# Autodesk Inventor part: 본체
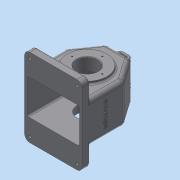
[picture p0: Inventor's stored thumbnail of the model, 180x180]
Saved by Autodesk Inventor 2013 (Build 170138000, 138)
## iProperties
Created: 2016-12
Part Number: 본체
Material: 일반
Document SubType Name: Modeling
Designer: dgall
Density: 1 g/cm^3
Author: dgall
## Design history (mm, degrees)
sketch "스케치1"
  geometry: L1 (-23.491, 85)-(-55, 40); L2 (-55, 40)-(-55, -40); L3 (-55, -40)-(55, -40); L4 (55, -40)-(55, 40); L5 (55, 40)-(23.491, 85); L6 (23.491, 85)-(-23.491, 85); L7 (-20.888, 80)-(-50, 38.424); L8 (-50, 38.424)-(-50, -40); L9 (50, -40)-(50, 38.424); L10 (50, 38.424)-(20.888, 80); L11 (20.888, 80)-(-20.888, 80); 4 further points
  constraints: 22 end point, 3 midpoint, 3 point on line, 2 vertical, 2 vertical alignment, 1 equal length, 1 horizontal, 1 horizontal alignment, 1 perpendicular, 3 other
  dimensions: "d0" = 80 distance of L3.end L4.end; "d2" = 35 deg angle of L2 L1; "d4" = 35 deg angle of L4 L5; "d6" = 125 distance between parallel lines of L3 L6; "d7" = 110 distance of L2.end L3.end; "d8" = 5 distance between parallel lines of L5 L10; "d9" = 5 distance between parallel lines of L1 L7
extrude "돌출1" new body sketch "스케치1" stored distance "d10" = 77; taper "d11" = 0 deg
extrude "돌출2" cut sketch "스케치1" stored distance "d12" = 67; taper "d13" = 0 deg
sketch "스케치2"
  geometry: L1 (85, -38.5)-(-40, -38.5) reference; L2 (-40, -38.5)-(-40, -33.5) reference; L3 (-40, -33.5)-(80, -33.5) reference; L4 (80, -33.5)-(80, 33.5) reference; L5 (80, 33.5)-(-40, 33.5) reference; L6 (-40, 33.5)-(-40, 38.5) reference; L7 (-40, 38.5)-(85, 38.5) reference; L8 (85, 38.5)-(85, -38.5) reference; L9 (25, 38.5)-(25, -38.5); L10 (-40, -33.5)-(-40, 33.5) reference; L11 (66, 33.5)-(52, 19.5); L12 (52, 19.5)-(25, 19.5); L13 (25, 38.5)-(25, 43.5); L14 (25, 43.5)-(62.5, 43.5); L15 (62.5, 43.5)-(62.5, 38.5); L16 (66, 33.5)-(66, 38.5); L17 (62.5, 38.5)-(66, 38.5); 1 further point
  constraints: 16 end point, 6 perpendicular, 6 point on line, 1 collinear
  dimensions: "d14" = 65 distance between parallel lines of L10 L9; "d16" = 24 distance between parallel lines of L12 L14; "d17" = 45 deg angle of L12 L11; "d18" = 5 distance from line of L14.end L7; "d19" = 27 distance from line of L9 L11.end; "d20" = 37.5 distance between parallel lines of L9 L15
revolve "회전1" sketch "스케치2" stored, may be unused: angle "d21" = 90 deg
node "작업 평면1"
sketch "스케치3" dims "d25" = 52
  geometry: C1 r 37.5 at (0, 25) reference; C2 r 20 at (0, 25); C3 r 31 at (0, 25); 3 further points
  constraints: 3 coincident, 2 centre point, 2 vertical alignment, 2 other
  dimensions: "d23" = 62 diameter of C3; "d26" = 40 diameter of C2
extrude "돌출3" join sketch "스케치3" stored distance "d27" = 67; taper "d28" = 0 deg
extrude "돌출4" cut sketch "스케치3" stored distance "d29" = 67; taper "d30" = 0 deg
hole "구멍1" sketch "스케치3" diameter "d31" = 2.459; stored, may be unused: countersink angle "d35" = 90 deg, drill point angle "d37" = 118 deg; dims "d32" = 6, "d33" = 4, "d34" = 2, "d36" = 8
sketch "스케치4" dims "d41" = 58
  geometry: C1 r 20 at (0, 0) reference; C2 r 37.5 at (0, 0) reference; 3 further points
  constraints: 2 vertical alignment, 1 coincident, 2 other
hole "구멍2" sketch "스케치4" at (0, 29) diameter "d43" = 2.459; stored, may be unused: countersink angle "d47" = 90 deg, drill point angle "d49" = 118 deg; dims "d44" = 6, "d45" = 4, "d46" = 2, "d48" = 8
sketch "스케치5"
  geometry: L1 (110, -77)-(110, 0) reference; L2 (0, 0)-(110, 0) reference; L3 (0, -77)-(0, 0) reference; L4 (110, -77)-(0, -77) reference; L5 (0, 36.5)-(110, 36.5); L6 (110, 36.5)-(110, -113.5); L7 (110, -113.5)-(0, -113.5); L8 (0, -113.5)-(0, 36.5); 3 further points
  constraints: 8 end point, 2 midpoint, 2 parallel, 1 horizontal, 1 horizontal alignment, 1 perpendicular, 1 vertical alignment
  dimensions: "d53" = 110 distance of L5.start L5.end; "d55" = 150 distance of L5.end L6.end
extrude "돌출5" join sketch "스케치5" distance "d56" = 15; taper "d57" = 0 deg
node "작업 평면2"
sketch "스케치6"
  geometry: L1 (-55, 40)-(-23.491, 85) reference; L2 (-23.491, 85)-(23.491, 85) reference; L3 (23.491, 85)-(55, 40) reference; L4 (55, 40)-(55, -40) reference; L5 (55, -40)-(50, -40) reference; L6 (50, -40)-(50, 38.424) reference; L7 (50, 38.424)-(20.888, 80) reference; L8 (20.888, 80)-(-20.888, 80) reference; L9 (-20.888, 80)-(-50, 38.424) reference; L10 (-50, 38.424)-(-50, -40) reference; L11 (-50, -40)-(-55, -40) reference; L12 (-55, -40)-(-55, 40) reference; L13 (-12.5, 85)-(-12.5, 100); L14 (-12.5, 100)-(12.5, 100); L15 (12.5, 100)-(12.5, 85); L16 (7.5, 85)-(7.5, 95); L17 (7.5, 95)-(-7.5, 95); L18 (-7.5, 95)-(-7.5, 85); L19 (50, -40)-(-50, -40) reference; 3 further points
  constraints: 12 end point, 4 point on line, 3 perpendicular, 2 midpoint, 2 vertical alignment, 1 parallel, 2 other
  dimensions: "d59" = 25 distance of L13.end L14.end; "d61" = 15 distance of L16.end L17.end; "d62" = 140 distance between parallel lines of L14 L19
extrude "돌출6" join sketch "스케치6" distance "d63" = 8; taper "d64" = 0 deg
node "작업 평면3"
sketch "스케치7"
  geometry: L1 (-36.5, -80)-(-36.5, -65) reference; L2 (113.5, -80)-(-36.5, -80) reference; L3 (0, -65)-(0, 0) reference; 2 further points
  constraints: 1 other
  dimensions: "d67" = 45 distance from line of L2 point (38.5, -35); "d68" = 38.5 distance from line of point (38.5, -35) L3
feature "엠보싱1" sketch "스케치7" dims "d69" = 0.5, "d70" = 0
fillet "모깎기1" dims "d71" = 10, "d72" = 3
fillet "모깎기2" dims "d73" = 8, "d74" = 3
fillet "모깎기3" dims "d75" = 10
sketch "스케치8"
  geometry: L1 (10, -36.5)-(100, -36.5) reference; L2 (110, -26.5)-(110, 8) reference; L3 (8, 0)-(102, 0) reference; L4 (0, 8)-(0, -26.5) reference; A1 r 10 centre (10, 103.5) between (10, 113.5) and (0, 103.5) reference; A2 r 10 centre (100, 103.5) between (110, 103.5) and (100, 113.5) reference; A3 r 10 centre (10, -26.5) between (0, -26.5) and (10, -36.5) reference; A4 r 10 centre (100, -26.5) between (100, -36.5) and (110, -26.5) reference; A5 r 8 centre (102, 8) between (102, 0) and (110, 8) reference; A6 r 8 centre (8, 8) between (0, 8) and (8, 0) reference; 1 further point
hole "구멍3" sketch "스케치8" at (100, 103.5), (10, 103.5), (10, -26.5), (100, -26.5) diameter "d76" = 5; stored, may be unused: countersink angle "d80" = 90 deg, drill point angle "d82" = 118 deg; dims "d77" = 6, "d78" = 12, "d79" = 5, "d81" = 8
fillet "모깎기4" dims "d83" = 8, "d84" = 3
fillet "모깎기5" dims "d85" = 1
fillet "모깎기6" dims "d86" = 1
fillet "모깎기7" dims "d87" = 1
fillet "모깎기8" dims "d88" = 3
chamfer "모따기1" distance "d89" = 1; stored, may be unused: second distance "d90" = 2, angle "d91" = 45 deg
node "솔리드1"
pattern_circular "원형 패턴1" dims angle "d39" = 360 deg
pattern_circular "원형 패턴2" dims angle "d51" = 360 deg
mirror "대칭1"
node "투영된 루프1"
node "절단 모서리 투영1"
node "절단 모서리 투영2"
other parameters: "d58" = 18
